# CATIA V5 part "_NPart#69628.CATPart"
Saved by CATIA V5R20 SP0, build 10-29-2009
Part number: 30-3IMAN8X3-80º
Revision: ANY
Definition: UNKNOWN
Nomenclature: 30-3IMAN8X3-80º
Source: Unknown
Bounding box of the stored display mesh (mm): x -3.804 to 3.804, y 0 to 3, z -4 to 4
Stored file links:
  C:\Users\Utente\Desktop\IO LAVORO\3D X SITO CF\CUMSA\3D files CC\CCHS5328\_NPart#69628.CATPart
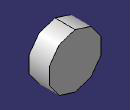
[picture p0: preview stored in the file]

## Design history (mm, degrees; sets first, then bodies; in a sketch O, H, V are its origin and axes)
Body1 "Saliente-Extruir1" (main body)
  Solid1: solid without history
